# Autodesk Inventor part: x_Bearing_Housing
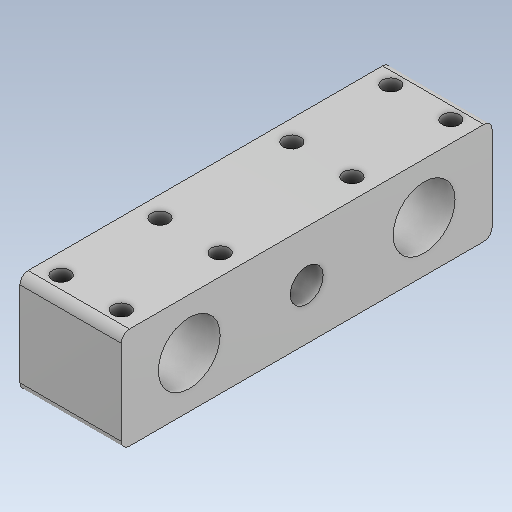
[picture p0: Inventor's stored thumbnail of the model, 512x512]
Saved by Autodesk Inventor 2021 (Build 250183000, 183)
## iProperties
Created: 2026-10
Part Number: x_Bearing_Housing
Material: Steel
Document SubType Name: Modeling
Designer: hp
Density: 7.85 g/cm^3
Appearance: Default
Author: hp
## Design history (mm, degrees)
feature "Body1"
body "Solid1"
